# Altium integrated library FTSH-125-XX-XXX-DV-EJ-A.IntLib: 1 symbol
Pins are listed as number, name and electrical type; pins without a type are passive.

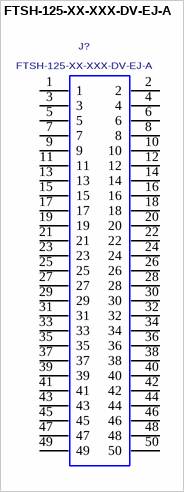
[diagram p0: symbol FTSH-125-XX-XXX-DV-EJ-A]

## FTSH-125-XX-XXX-DV-EJ-A
designator J?
0.050 INCH DOUBLE VERTICAL SMT TERMINAL STIP.; MANUFACTURER: SAMTEC
footprint FTSH-125-XX-XXX-DV-EJ-A
pins: 1, 2, 3, 4, 5, 6, 7, 8, 9, 10, 11, 12, 13, 14, 15, 16, 17, 18, 19, 20, 21, 22, 23, 24, 25, 26, 27, 28, 29, 30, 31, 32, 33, 34, 35, 36, 37, 38, 39, 40, 41, 42, 43, 44, 45, 46, 47, 48, 49, 50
